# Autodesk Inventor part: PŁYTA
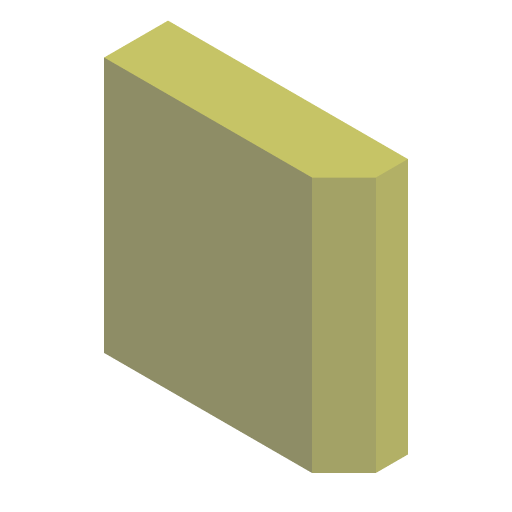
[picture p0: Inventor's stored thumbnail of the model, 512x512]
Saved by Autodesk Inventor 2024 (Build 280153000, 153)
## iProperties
Company: ATC
Shininess: 20.0
Length Units: 11269
Angle Units: 11279
Time Units: 11290
Mass Units: 11283
Length Display Precision: 3
Angle Display Precision: 2
Compacted: True
Created: 2023-03
Part Number: PŁYTA
Document SubType Name: Modeling
Designer: Andrzej Jaskulski
Material: Kurs-AJ
Density: 1 g/cm^3
Mass: 116 g
Surface Area: 176.314 cm^2
Volume: 116 cm^3
Appearance: Przezroczyste — żółte
Checked By: A.J.
Engr Approved By: Andrzej Jaskulski
Mfg Approved By: Andrzej Jaskulski
Authority: A.J.
Density: 0.0
Volumn: 0.0
Area: 0.0
PropertySet Name: Model Information
Control State: 0
Master: False
Checked Out: False
Title: A.J.: Kurs R2024-MEP
Author: Andrzej Jaskulski
Revision Number: 1/24
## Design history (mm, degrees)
node "Wyciągnięcie" dims "d4" = 20, "d5" = 0
node "Fazowanie1" dims "d6" = 10, "d7" = 10, "d42" = 45 deg
node "Bryła1"
node "Korpusy bryłowe"
node "Korpusy powierzchniowe"
sketch "Sketch1"
  geometry: L1 (-25, 55)-(-25, -25); L2 (50, 55)-(-25, 55); L3 (50, -25)-(50, 55); L4 (-25, -25)-(50, -25)
  constraints: 8 end point, 2 horizontal, 2 vertical, 1 other
  dimensions: "d1" = 80 distance of L3.start L2.start; "d3" = 75 distance of L2.start L1.start
other parameters: "d2" = 75 (derived), "d8" = 0, "d12" = 6.5 (derived), "d14" = 8.5 (derived), "d29" = 46 (derived), "d31" = 43 (derived), "d33" = 21.5 (derived), "d35" = 23 (derived), "d37" = 7.679 (derived)
